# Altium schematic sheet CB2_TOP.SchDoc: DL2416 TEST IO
size A2; Engineer: SHOWELL; DocumentNumber: 1; Revision: 1.00; SheetNumber: 1; SheetTotal: 1; PageSetup: Record=PageOptions|CenterHorizontal=True|CenterVertical=True|PrintScale=1.47|XCorrection=1.00|YCorrection=1.00|PrintKind=0|BorderSize=5000000|LeftOffset=0|BottomOffset=0|Orientation=2|PaperLength=1000|PaperWidth=1000|Scale=100|PaperSource=7|PrintQuality=-4|MediaType=1|DitherType=10|PaperKind=A2|PrintScaleMode=1
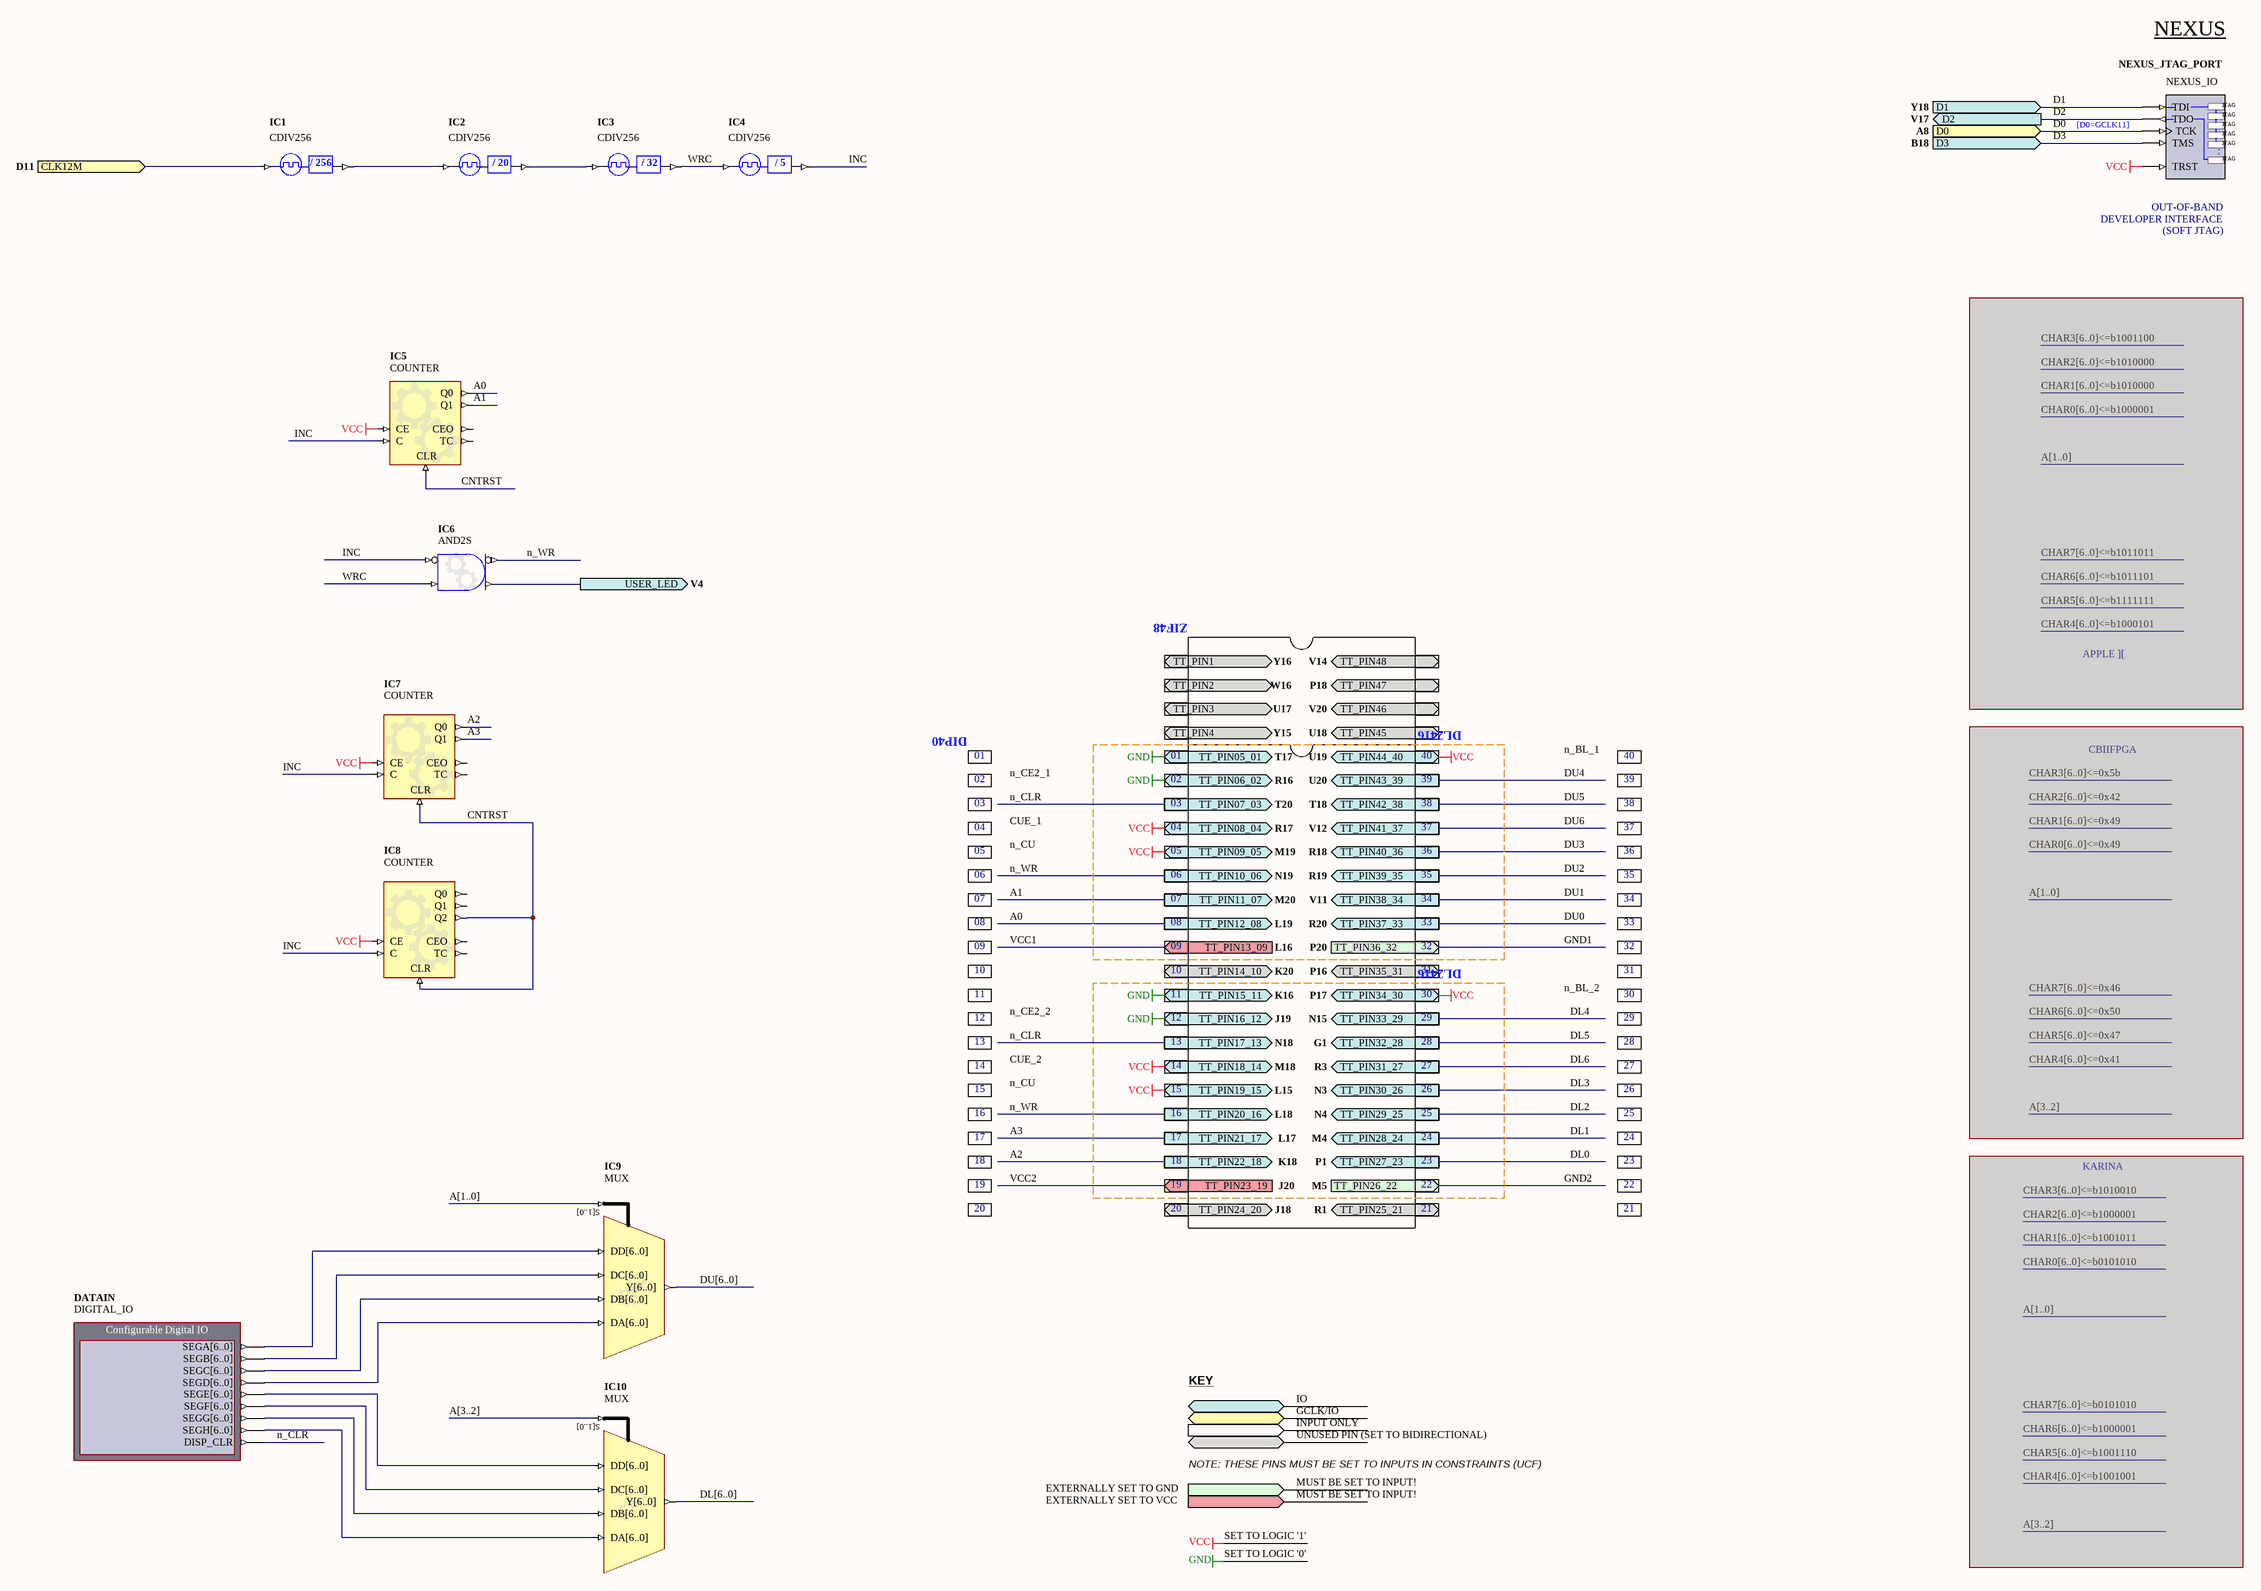
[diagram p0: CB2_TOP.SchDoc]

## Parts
DATAIN  DIGITAL_IO
IC1  CDIV256
IC2  CDIV256
IC3  CDIV256
IC4  CDIV256
IC5  COUNTER
IC6  AND2S
IC7  COUNTER
IC8  COUNTER
IC9  MUX
IC10  MUX
NEXUS_JTAG_PORT  NEXUS_IO

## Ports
CLK12M (in, see D11), D0 (in, see A8), D1 (in, see Y18), D2 (out, see V17), D3 (in, see B18), TT_PIN1 (bidir, see Y16), TT_PIN2 (bidir, see W16), TT_PIN3 (bidir, see U17), TT_PIN4 (bidir, see Y15), TT_PIN05_01 (out, see T17), TT_PIN06_02 (out, see R16), TT_PIN07_03 (out, see T20), TT_PIN08_04 (out, see R17), TT_PIN09_05 (out, see M19), TT_PIN10_06 (out, see N19), TT_PIN11_07 (out, see M20), TT_PIN12_08 (out, see L19), TT_PIN13_09 (in, see L16), TT_PIN14_10 (bidir, see K20), TT_PIN15_11 (out, see K16), TT_PIN16_12 (out, see J19), TT_PIN17_13 (out, see N18), TT_PIN18_14 (out, see M18), TT_PIN19_15 (out, see L15), TT_PIN20_16 (out, see L18), TT_PIN21_17 (out, see L17), TT_PIN22_18 (out, see K18), TT_PIN23_19 (in, see J20), TT_PIN24_20 (bidir, see J18), TT_PIN25_21 (bidir, see R1), TT_PIN26_22 (in, see M5), TT_PIN27_23 (out, see P1), TT_PIN28_24 (out, see M4), TT_PIN29_25 (out, see N4), TT_PIN30_26 (out, see N3), TT_PIN31_27 (out, see R3), TT_PIN32_28 (out, see G1), TT_PIN33_29 (out, see N15), TT_PIN34_30 (out, see P17), TT_PIN35_31 (bidir, see P16), TT_PIN36_32 (in, see P20), TT_PIN37_33 (out, see R20), TT_PIN38_34 (out, see V11), TT_PIN39_35 (out, see R19), TT_PIN40_36 (out, see R18), TT_PIN41_37 (out, see V12), TT_PIN42_38 (out, see T18), TT_PIN43_39 (out, see U20), TT_PIN44_40 (out, see U19), TT_PIN45 (bidir, see U18), TT_PIN46 (bidir, see V20), TT_PIN47 (bidir, see P18), TT_PIN48 (bidir, see V14), USER_LED (out, see V4)

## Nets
GND: port TT_PIN16_12, port TT_PIN15_11, port TT_PIN06_02, port TT_PIN05_01
VCC: IC5.CE IC7.CE IC8.CE NEXUS_JTAG_PORT.TRST ; port TT_PIN09_05, port TT_PIN19_15, port TT_PIN34_30, port TT_PIN44_40, port TT_PIN18_14, port TT_PIN08_04
A0: IC5.Q0 ; port TT_PIN12_08
A1: IC5.Q1 ; port TT_PIN11_07
A2: IC7.Q0 ; port TT_PIN22_18
A3: IC7.Q1 ; port TT_PIN21_17
CLK12M: IC1.CLKIN ; port CLK12M
CNTRST: IC5.CLR IC7.CLR IC8.CLR IC8.Q2
D0: NEXUS_JTAG_PORT.TCK ; port D0
D1: NEXUS_JTAG_PORT.TDI ; port D1
D2: NEXUS_JTAG_PORT.TDO ; port D2
D3: NEXUS_JTAG_PORT.TMS ; port D3
INC: IC4.CLKDV IC5.C IC6.I0 IC7.C IC8.C
n_CLR: DATAIN.DISP_CLR ; port TT_PIN17_13, port TT_PIN07_03
n_WR: IC6.NO ; port TT_PIN20_16, port TT_PIN10_06
USER_LED: IC6.O ; port USER_LED
WRC: IC3.CLKDV IC4.CLKIN IC6.I1
NetIC1_CLKDV: IC1.CLKDV IC2.CLKIN
NetIC2_CLKDV: IC2.CLKDV IC3.CLKIN

Not connected (* = marked no-connect by the designer): DATAIN SEGA[6..0] SEGB[6..0] SEGC[6..0] SEGD[6..0] SEGE[6..0] SEGF[6..0] SEGG[6..0] SEGH[6..0]; IC5 CEO TC; IC7 CEO TC; IC8 CEO Q0 Q1 TC; IC9 DA[6..0] DB[6..0] DC[6..0] DD[6..0] S[1..0] Y[6..0]; IC10 DA[6..0] DB[6..0] DC[6..0] DD[6..0] S[1..0] Y[6..0]

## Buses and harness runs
bus A[1..0]
bus A[3..2]
bus DL[6..0]
bus DU[6..0]

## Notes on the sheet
- NEXUS
- (near NEXUS_JTAG_PORT) [D0=GCLK11]
- DEVELOPER INTERFACE
- (near NEXUS_JTAG_PORT) OUT-OF-BAND
- (SOFT JTAG)
- ZIF48
- APPLE ][
- DIP40
- DL2416
- 01
- 02
- 40
- 39
- CBIIFPGA
- 03
- 04
- 38
- 37
- 05
- 06
- 07
- 36
- 35
- 34
- 08
- 09
- 33
- 32
- 10
- 11
- 12
- 31
- 30
- 29
- 13
- 14
- 28
- 27
- 15
- 16
- 17
- 26
- 25
- 24
- 18
- 19
- 23
- 22
- KARINA
- 20
- 21
- KEY
- IO
- GCLK/IO
- INPUT ONLY
- UNUSED PIN (SET TO BIDIRECTIONAL)
- EXTERNALLY SET TO GND
- NOTE: THESE PINS MUST BE SET TO INPUTS IN CONSTRAINTS (UCF)
- MUST BE SET TO INPUT!
- EXTERNALLY SET TO VCC
- VCC
- GND
- SET TO LOGIC '1'
- SET TO LOGIC '0'
- Labels drawn without touching a wire or pin: CUE_1, CUE_2, n_BL_1, n_BL_2, n_CE2_1, n_CE2_2, n_CU

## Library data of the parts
DATAIN = DIGITAL_IO: Configurable Digital IO; NEXUS_CORE: Instrument; NEXUS_JTAG_DEVICE: True; NEXUS_JTAG_ORDER: 0; ConfigurationParameters: {}Version[2.0]{}StorageType[3]{}InterfaceType[Parallel]{}SchCompWidth[140]{}NoInputs[ ]{}Output0Name[SEGA{1}6..0{2}]{}Output0Width[7]{}Output0InitValue[91]{}Output0Kind[Numeric]{}Output0NumRadix[Binary]{}Output1Name[SEGB{1}6..0{2}]{}Output1Width[7]{}Output1InitValue[66]{}Output1Kind[Numeric]{}Output1NumRadix[Binary]{}Output2Name[SEGC{1}6..0{2}]{}Output2Width[7]{}Output2InitValue[73]{}Output2Kind[Numeric]{}Output2NumRadix[Binary]{}Output3Name[SEGD{1}6..0{2}]{}Output3Width[7]{}Output3InitValue[73]{}Output3Kind[Numeric]{}Output3NumRadix[Binary]{}Output4Name[SEGE{1}6..0{2}]{}Output4Width[7]{}Output4InitValue[70]{}Output4Kind[Numeric]{}Output4NumRadix[Binary]{}Output5Name[SEGF{1}6..0{2}]{}Output5Width[7]{}Output5InitValue[80]{}Output5Kind[Numeric]{}Output5NumRadix[Binary]{}Output6Name[SEGG{1}6..0{2}]{}Output6Width[7]{}Output6InitValue[71]{}Output6Kind[Numeric]{}Output6NumRadix[Binary]{}Output7Name[SEGH{1}6..0{2}]{}Output7Width[7]{}Output7InitValue[65]{}Output7Kind[Numeric]{}Output7NumRadix[Binary]{}Output8Name[DISP_CLR]{}Output8Width[1]{}Output8InitValue[15]{}Output8Kind[Numeric]{}Output8NumRadix[Binary]{}Designator[DATAIN]{}InternalID[0]{}
IC1 = CDIV256DC50: Clock Divider by 256 with 50% Duty Cycle Output; DivisorRate: 256; ArchiveName: GENERIC; VHDLIB_SIM: GENERIC_LIB; DutyCycle: 50
IC2 = CDIV20DC50: Clock Divider by 20 with 50% Duty Cycle Output; DivisorRate: 20; ArchiveName: GENERIC; VHDLIB_SIM: GENERIC_LIB; DutyCycle: 50
IC3 = CDIV32DC50: Clock Divider by 32 with 50% Duty Cycle Output; DivisorRate: 32; ArchiveName: GENERIC; VHDLIB_SIM: GENERIC_LIB; DutyCycle: 50
IC4 = CDIV5: Clock Divider by 5; DivisorRate: 5; ArchiveName: GENERIC; VHDLIB_SIM: GENERIC_LIB
IC5 IC7 = COUNTER: Configurable Counter; ConfiguratorName: GENERIC_COUNTER; ConfigurationParameters: {}Version[1.0]{}Type[Binary]{}SyncReset[False]{}NegativeClockEdge[False]{}FixedDirection[True]{}IsIncrement[True]{}SignalWidth[2]{}MaxValue[3]{}BusOutput[False]{}Loadable[False]{}BusInput[False]{}ShowPinNames[True]{}
IC6 = GATE: Configurable Generic Gate; ConfiguratorName: GENERIC_GATE; ConfigurationParameters: {}Version[1.1]{}GateKind[AND]{}BusInput[False]{}GateInputType[Bit]{}GateOutputOption[Normal/Inverted]{}BusWidth[8]{}RegisterOutputs[False]{}NegativeClockEdge[False]{}InputCount[2]{}InputInvert0[True]{}InputInvert1[False]{}
IC8 = COUNTER: Configurable Counter; ConfiguratorName: GENERIC_COUNTER; ConfigurationParameters: {}Version[1.0]{}Type[Binary]{}SyncReset[False]{}NegativeClockEdge[False]{}FixedDirection[True]{}IsIncrement[True]{}SignalWidth[3]{}MaxValue[7]{}BusOutput[False]{}Loadable[False]{}BusInput[False]{}ShowPinNames[True]{}
IC9 IC10 = MUX: Configurable Mutliplexer; ConfiguratorName: GENERIC_MULTIPLEXER; ConfigurationParameters: {}Version[1.0]{}ShowEnable[False]{}BusInputs[True]{}BusOutputs[True]{}SignalWidth[7]{}Type[Multiplexer]{}RegisterOutputs[False]{}NegativeClockEdge[True]{}ShowPinNames[True]{}InvertSingleSignal[False]{}SignalCount[4]{}Invert0[False]{}Invert1[False]{}Invert2[False]{}Invert3[False]{}
NEXUS_JTAG_PORT = NEXUS_JTAG_PORT: Soft Nexus-Chain Connector; NEXUS_JTAG_CONNECTOR: True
